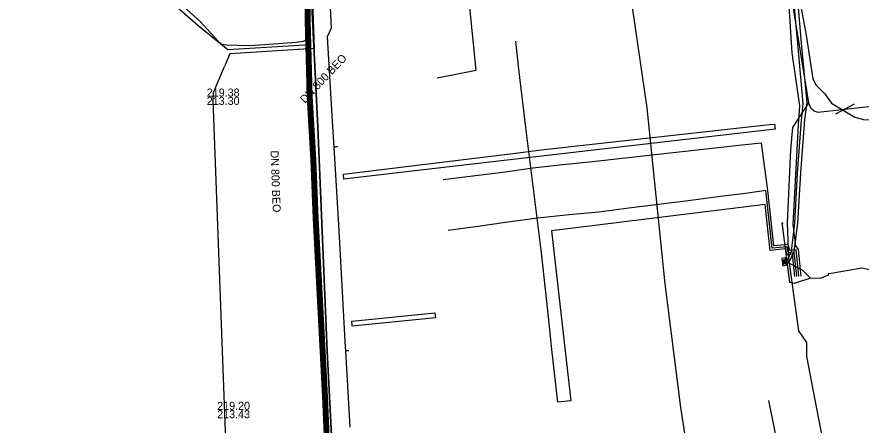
# Model space of a CAD drawing. Extents: x -599951 to -598963, y -1164095 to -1162939.
# Drawn here: x -599256.8 to -599172.5, y -1163441.6 to -1163400.9 of the extents above; entities that cross this region are included whole.
import ezdxf

# ---------------------------------------------------------------- set-up
doc = ezdxf.new("R2010")
doc.units = 0
for name, color, linetype in [('28', 7, 'Continuous'), ('Level 3', 7, 'Continuous'), ('Vrstva 1', 7, 'Continuous'), ('Vrstva 12', 7, 'Continuous'), ('Vrstva 42', 7, 'Continuous'), ('Vrstva 43', 7, 'Continuous'), ('Vrstva 44', 7, 'Continuous'), ('Vrstva 55', 7, 'Continuous'), ('Vrstva 58', 7, 'Continuous')]:
    doc.layers.add(name, color=color, linetype=linetype)

# ---------------------------------------------------------------- blocks, each defined once
blk = doc.blocks.new('NN620')
at = {"layer": '28'}
for points in [[(0.752, 0.004), (-0.748, 0.004)], [(-0.748, 0.004), (-0.748, -0.746)], [(0.752, -0.746), (0.752, 0.004)], [(-0.748, -0.746), (0.752, -0.746)], [(0.368, -0.18), (-0.376, -0.18)], [(-0.376, -0.18), (-0.376, -0.558)], [(-0.376, -0.558), (0.368, -0.558)], [(0.321, -0.227), (-0.329, -0.227)], [(-0.329, -0.227), (-0.329, -0.51)], [(-0.329, -0.51), (0.321, -0.51)], [(0.274, -0.274), (-0.281, -0.274)], [(-0.281, -0.274), (-0.281, -0.463)], [(-0.281, -0.463), (0.274, -0.463)], [(0.227, -0.321), (-0.234, -0.321)], [(-0.234, -0.321), (-0.234, -0.416)], [(-0.234, -0.416), (0.227, -0.416)], [(-0.193, -0.369), (0.185, -0.369)], [(0.227, -0.416), (0.227, -0.321)], [(0.274, -0.463), (0.274, -0.274)], [(0.321, -0.51), (0.321, -0.227)], [(0.368, -0.558), (0.368, -0.18)]]:
    blk.add_lwpolyline(points, dxfattribs=at)

msp = doc.modelspace()

# ---------------------------------------------------------------- linework, layer by layer
at = {"layer": 'Level 3'}
for points in [[(-599181.66, -1163411.62), (-599181.16, -1163411.56), (-599181.1, -1163412.06), (-599216.79, -1163416.18), (-599224.17, -1163417.06), (-599224.2, -1163416.56), (-599216.85, -1163415.68), (-599207.28, -1163414.5), (-599204.46, -1163414.12)], [(-599223.37, -1163431.24), (-599215.08, -1163430.4), (-599215.02, -1163430.9), (-599223.34, -1163431.74)]]:
    msp.add_lwpolyline(points, close=True, dxfattribs=at)
at = {"layer": 'Vrstva 1'}
for p, q in [((-599210.95, -1163406.17), (-599214.67, -1163369.26)), ((-599214.87, -1163406.93), (-599210.95, -1163406.17)), ((-599181.75, -1163439.17), (-599174.22, -1163476.13))]:
    msp.add_line(p, q, dxfattribs=at)
at = {"layer": 'Vrstva 42'}
for p, q in [((-599173.184, -1163409.591), (-599175.046, -1163410.565)), ((-599177.56, -1163426.93), (-599179.2, -1163427.48)), ((-599175.808, -1163426.509), (-599175.79, -1163426.66))]:
    msp.add_line(p, q, dxfattribs=at)
for points in [[(-599224.61, -1163458.23), (-599225.84, -1163434.22), (-599226.77, -1163411.87), (-599227.39, -1163399.73), (-599228, -1163379.96), (-599229.84, -1163349.61), (-599231.04, -1163328.77), (-599232.25, -1163300.34), (-599232.78, -1163281.98), (-599233.12, -1163279.09), (-599233.85, -1163272.58), (-599234.55, -1163261.34), (-599236.04, -1163234.14), (-599238.28, -1163193.96)], [(-599211.757, -1163588.838), (-599211.66, -1163589.578), (-599212.89, -1163589.29), (-599214.35, -1163588.59), (-599214.84, -1163577.9), (-599216.2, -1163560.96), (-599216.62, -1163543.04), (-599219.31, -1163511.2), (-599221.85, -1163490.32), (-599224.61, -1163458.23), (-599225.84, -1163434.22), (-599226.77, -1163411.87), (-599227.39, -1163399.73), (-599228, -1163379.96), (-599229.84, -1163349.61), (-599231.04, -1163328.77), (-599232.25, -1163300.34), (-599232.78, -1163281.98), (-599233.12, -1163279.09), (-599233.85, -1163272.58), (-599234.55, -1163261.34), (-599236.04, -1163234.14), (-599238.28, -1163193.96)], [(-599211.757, -1163588.838), (-599211.66, -1163589.578), (-599212.89, -1163589.29), (-599214.35, -1163588.59), (-599214.84, -1163577.9), (-599216.2, -1163560.96), (-599216.62, -1163543.04), (-599219.31, -1163511.2), (-599221.85, -1163490.32), (-599224.61, -1163458.23), (-599225.84, -1163434.22), (-599226.77, -1163411.87), (-599227.39, -1163399.73), (-599228, -1163379.96), (-599229.84, -1163349.61), (-599231.04, -1163328.77), (-599232.25, -1163300.34), (-599232.78, -1163281.98), (-599233.12, -1163279.09), (-599233.85, -1163272.58), (-599234.55, -1163261.34), (-599236.04, -1163234.14), (-599238.28, -1163193.96)], [(-599214.49, -1163593.34), (-599214.35, -1163588.59), (-599214.84, -1163577.9), (-599216.2, -1163560.96), (-599216.62, -1163543.04), (-599219.31, -1163511.2), (-599221.85, -1163490.32), (-599224.61, -1163458.23), (-599225.84, -1163434.22), (-599226.77, -1163411.87), (-599227.39, -1163399.73), (-599228, -1163379.96), (-599229.84, -1163349.61), (-599231.04, -1163328.77), (-599232.25, -1163300.34), (-599232.78, -1163281.98), (-599233.12, -1163279.09), (-599233.85, -1163272.58), (-599234.55, -1163261.34), (-599236.04, -1163234.14), (-599238.28, -1163193.96)], [(-599214.49, -1163593.34), (-599214.35, -1163588.59), (-599214.84, -1163577.9), (-599216.2, -1163560.96), (-599216.62, -1163543.04), (-599219.31, -1163511.2), (-599221.85, -1163490.32), (-599224.61, -1163458.23), (-599225.84, -1163434.22), (-599226.77, -1163411.87), (-599227.39, -1163399.73), (-599228, -1163379.96), (-599229.84, -1163349.61), (-599231.04, -1163328.77), (-599232.25, -1163300.34), (-599232.78, -1163281.98), (-599233.12, -1163279.09), (-599233.85, -1163272.58), (-599234.55, -1163261.34), (-599236.04, -1163234.14), (-599238.28, -1163193.96)], [(-599224.61, -1163458.23), (-599225.84, -1163434.22), (-599226.77, -1163411.87), (-599227.39, -1163399.73), (-599228, -1163379.96), (-599229.84, -1163349.61), (-599231.04, -1163328.77), (-599232.25, -1163300.34), (-599232.78, -1163281.98), (-599233.12, -1163279.09), (-599233.85, -1163272.58), (-599234.55, -1163261.34), (-599236.04, -1163234.14), (-599238.28, -1163193.96)], [(-599229.322, -1163278.551), (-599233.12, -1163279.09), (-599232.78, -1163281.98), (-599232.25, -1163300.34), (-599231.04, -1163328.77), (-599229.84, -1163349.61), (-599228, -1163379.96), (-599227.39, -1163399.73), (-599226.77, -1163411.87), (-599225.84, -1163434.22), (-599224.61, -1163458.23)], [(-599190.14, -1163320.95), (-599191.11, -1163322.64), (-599190.28, -1163328.52), (-599190.06, -1163330.57), (-599190.68, -1163331.26), (-599188.51, -1163342.56), (-599188.29, -1163343.98), (-599185.98, -1163362.49), (-599184.02, -1163378.38), (-599182.58, -1163394.45), (-599182.18, -1163395.08), (-599179.86, -1163397.7), (-599179.27, -1163398.3), (-599178.66, -1163399.12), (-599178.03, -1163402.48), (-599177.31, -1163407.06), (-599177, -1163407.69)], [(-599179.999, -1163425.339), (-599179.885, -1163425.189), (-599179.74, -1163424.96), (-599179.46, -1163424.24), (-599179.11, -1163421.45), (-599178.85, -1163416.47), (-599178.46, -1163411.18), (-599178.28, -1163409.5), (-599178.83, -1163403.52), (-599179.22, -1163399.16), (-599179.74, -1163396.16), (-599178.925, -1163394.748)], [(-599178.77, -1163394.891), (-599179.5, -1163396.12), (-599178.86, -1163399.14), (-599178.5, -1163403.47), (-599177.93, -1163409.41), (-599178.17, -1163411.12), (-599178.56, -1163416.44), (-599178.84, -1163421.44), (-599179.23, -1163424.29), (-599179.56, -1163425.04), (-599179.816, -1163425.393), (-599179.981, -1163425.494)], [(-599241.11, -1163399.01), (-599238.55, -1163401.29), (-599236.71, -1163403.33), (-599236.38, -1163403.59), (-599235.9, -1163403.66), (-599233.65, -1163403.73), (-599232.06, -1163403.61), (-599228.94, -1163403.38), (-599228.2, -1163403.28), (-599227.89, -1163403.11), (-599227.74, -1163402.67), (-599228.05, -1163397.73)], [(-599177, -1163407.69), (-599176.14, -1163408.56), (-599175.46, -1163409.48), (-599174.31, -1163410.18), (-599173.13, -1163410.88), (-599172.25, -1163411.1), (-599171.56, -1163411.13), (-599167.35, -1163411.12), (-599166.48, -1163411.1), (-599163.47, -1163410.88), (-599162.455, -1163410.965)], [(-599180.39, -1163421.37), (-599180.38, -1163421.4), (-599180.35, -1163421.5)], [(-599179.2, -1163427.48), (-599179.47, -1163427.41), (-599179.64, -1163427.34), (-599179.62, -1163427.33), (-599180.39, -1163421.37)], [(-599175.79, -1163426.66), (-599176.58, -1163426.98), (-599177.56, -1163426.93), (-599178.35, -1163426.15), (-599179.9, -1163425.34)], [(-599164.4, -1163437.31), (-599165.12, -1163432.72), (-599165.45, -1163430.95), (-599165.88, -1163429.98), (-599166.56, -1163429.06), (-599167.76, -1163427.79), (-599169.73, -1163426.5), (-599172.44, -1163425.96), (-599175.3, -1163426.445), (-599175.716, -1163426.498), (-599175.808, -1163426.509)], [(-599169.73, -1163426.5), (-599172.44, -1163425.96), (-599175.3, -1163426.445), (-599175.716, -1163426.498), (-599175.808, -1163426.509)], [(-599175.808, -1163426.509), (-599175.79, -1163426.66), (-599176.58, -1163426.98), (-599177.56, -1163426.93)]]:
    msp.add_lwpolyline(points, dxfattribs=at)
at = {"layer": 'Vrstva 44'}
for points in [[(-599238.757, -1163401.725), (-599246.32, -1163395.11), (-599248.23, -1163393.74), (-599250.84, -1163391.76), (-599251.5, -1163391.09), (-599251.8, -1163390.16), (-599251.93, -1163385.35), (-599252.39, -1163377.35), (-599252.65, -1163369.4), (-599252.9, -1163362.91), (-599253.51, -1163354.83), (-599253.79, -1163347.39), (-599253.99, -1163341.32), (-599254.31, -1163333.85), (-599254.28, -1163327.94), (-599254.76, -1163321.48), (-599255.22, -1163314.42), (-599256.34, -1163305.03), (-599256.84, -1163297.64), (-599256.823, -1163290.889)], [(-599227.34, -1163408.809), (-599227.54, -1163401.199), (-599227.58, -1163393.679), (-599227.21, -1163389.699), (-599227.72, -1163382.299), (-599227.74, -1163380.619), (-599227.912, -1163380.378), (-599228.227, -1163378.968), (-599228.239, -1163378.51), (-599228.469, -1163375.28), (-599228.749, -1163368.07), (-599228.929, -1163364.41), (-599229.499, -1163356.28), (-599230.079, -1163346.28), (-599230.499, -1163338.18), (-599230.839, -1163330.16), (-599231.819, -1163318.58)], [(-599230.467, -1163379.765), (-599228.144, -1163380.56), (-599228.136, -1163380.986), (-599228.12, -1163382.318), (-599227.611, -1163389.708), (-599227.98, -1163393.681), (-599227.94, -1163401.213), (-599227.74, -1163408.828), (-599227.39, -1163415.12), (-599227.13, -1163420.969), (-599226.69, -1163429.82), (-599226.22, -1163438.76), (-599225.759, -1163449.392), (-599225.366, -1163450.807), (-599225.691, -1163452.385), (-599225.19, -1163460.992), (-599224.75, -1163468.141), (-599224.35, -1163476.339), (-599223.968, -1163486.21), (-599223.187, -1163487.477), (-599219.377, -1163491.136)], [(-599230.543, -1163380.39), (-599229.863, -1163380.442), (-599228.727, -1163381.025), (-599228.643, -1163381.866), (-599228.024, -1163390.733), (-599227.547, -1163403.651), (-599235.772, -1163404.164), (-599238.757, -1163401.725)], [(-599230.528, -1163379.968), (-599229.747, -1163380.052), (-599228.351, -1163380.769), (-599228.245, -1163381.832), (-599227.624, -1163390.711), (-599227.133, -1163404.027), (-599235.582, -1163404.545), (-599236.113, -1163405.821)], [(-599225.559, -1163449.38), (-599226.02, -1163438.749), (-599226.49, -1163429.809), (-599226.93, -1163420.958), (-599227.19, -1163415.109), (-599227.54, -1163408.817), (-599227.74, -1163401.202), (-599227.78, -1163393.67), (-599227.411, -1163389.697), (-599227.92, -1163382.307), (-599227.94, -1163380.643)], [(-599235.65, -1163451.2), (-599237.219, -1163409.17), (-599237.183, -1163408.413), (-599236.113, -1163405.821)], [(-599225.36, -1163449.349), (-599225.82, -1163438.739), (-599226.29, -1163429.799), (-599226.73, -1163420.949), (-599226.99, -1163415.099), (-599227.34, -1163408.809)]]:
    msp.add_lwpolyline(points, dxfattribs=at)
at = {"layer": 'Vrstva 55'}
for points in [[(-599183.74, -1163485.49), (-599188.79, -1163450.9), (-599190.5, -1163439.86), (-599192.07, -1163427.52), (-599193.88, -1163409.95), (-599196.91, -1163389.13), (-599198.044, -1163380.488)], [(-599179.95, -1163393.29), (-599180.14, -1163394.15), (-599180.19, -1163395.52), (-599179.69, -1163397.03), (-599179.43, -1163399.17), (-599177.76, -1163409.44), (-599177.738, -1163409.537), (-599177.67, -1163409.723), (-599177.622, -1163409.807), (-599177.571, -1163409.895), (-599177.511, -1163409.974), (-599177.371, -1163410.115), (-599177.293, -1163410.176), (-599177.122, -1163410.277), (-599177.031, -1163410.316), (-599176.84, -1163410.37), (-599171.43, -1163409.79)], [(-599179.95, -1163393.29), (-599180.14, -1163394.15), (-599179.76, -1163395.36), (-599180.16, -1163395.76), (-599179.69, -1163397.03), (-599179.43, -1163399.17), (-599177.76, -1163409.44), (-599179.37, -1163411.92), (-599179.57, -1163414.14), (-599179.89, -1163421.43), (-599179.77, -1163424.95), (-599178.74, -1163432.21), (-599177.95, -1163433.36), (-599177.96, -1163434.77)], [(-599180.19, -1163393.53), (-599180.27, -1163394.36), (-599179.52, -1163395.24), (-599179.54, -1163395.71), (-599179.77, -1163399.24), (-599179.43, -1163404.44), (-599178.64, -1163409.73), (-599178.79, -1163411.64), (-599179.33, -1163421.6), (-599179.061, -1163423.712), (-599178.805, -1163424.078), (-599178.52, -1163426.75)], [(-599225.79, -1163394.96), (-599225.44, -1163401.99), (-599225.83, -1163402.86), (-599225.334, -1163411.264), (-599225.18, -1163413.87), (-599224.822, -1163413.798), (-599225.18, -1163413.87), (-599224.722, -1163421.627), (-599224.58, -1163424.03), (-599224.035, -1163433.816), (-599224.014, -1163434.201), (-599223.667, -1163434.15), (-599224.014, -1163434.201), (-599223.59, -1163441.83)], [(-599179.12, -1163426.781), (-599179.356, -1163424.564), (-599179.896, -1163424.644), (-599180.07, -1163424.02), (-599181.577, -1163424.169), (-599182.08, -1163419.58), (-599203.42, -1163422.22), (-599201.51, -1163439.19), (-599202.809, -1163439.331), (-599203.097, -1163436.697), (-599203.384, -1163434.063), (-599203.671, -1163431.428), (-599204.04, -1163428.048), (-599204.436, -1163424.42), (-599206.035, -1163411.628), (-599206.357, -1163408.847), (-599206.679, -1163406.066), (-599207.001, -1163403.284)], [(-599178.72, -1163426.76), (-599179.003, -1163424.108), (-599179.605, -1163424.197), (-599179.775, -1163423.589), (-599181.222, -1163423.732), (-599181.829, -1163418.185), (-599182.44, -1163413.46), (-599184.413, -1163413.682), (-599187.395, -1163414.009), (-599190.377, -1163414.336), (-599193.359, -1163414.663), (-599196.342, -1163414.99), (-599199.324, -1163415.317), (-599202.306, -1163415.644), (-599205.288, -1163415.971), (-599208.304, -1163416.39), (-599211.282, -1163416.757), (-599214.259, -1163417.128)], [(-599178.92, -1163426.77), (-599179.18, -1163424.336), (-599179.751, -1163424.42), (-599179.923, -1163423.804), (-599181.399, -1163423.95), (-599182.028, -1163418.207), (-599183.809, -1163418.46), (-599186.785, -1163418.837), (-599189.762, -1163419.213), (-599192.738, -1163419.589), (-599195.714, -1163419.966), (-599198.69, -1163420.342), (-599201.65, -1163420.62), (-599204.816, -1163420.94), (-599207.787, -1163421.357), (-599210.758, -1163421.773), (-599213.759, -1163422.184)], [(-599177.96, -1163434.77), (-599172.809, -1163461.537)]]:
    msp.add_lwpolyline(points, dxfattribs=at)
at = {"layer": 'Vrstva 58'}
for points in [[(-599223.108, -1163487.413), (-599223.869, -1163486.18), (-599224.25, -1163476.334), (-599224.65, -1163468.135), (-599225.09, -1163460.986), (-599225.591, -1163452.393), (-599225.263, -1163450.803), (-599225.659, -1163449.376), (-599226.12, -1163438.755), (-599226.59, -1163429.815), (-599227.03, -1163420.965), (-599227.29, -1163415.115), (-599227.64, -1163408.824), (-599227.84, -1163401.212), (-599227.88, -1163393.686), (-599227.51, -1163389.709), (-599228.02, -1163382.314), (-599228.04, -1163380.642), (-599228.188, -1163380.463), (-599228.529, -1163379.006), (-599228.539, -1163378.515), (-599228.77, -1163375.275), (-599228.891, -1163372.22)], [(-599222.952, -1163487.287), (-599223.671, -1163486.12), (-599224.05, -1163476.326), (-599224.45, -1163468.124), (-599224.89, -1163460.974), (-599225.389, -1163452.407), (-599225.057, -1163450.797), (-599225.461, -1163449.344), (-599225.92, -1163438.745), (-599226.39, -1163429.805), (-599226.83, -1163420.955), (-599227.09, -1163415.105), (-599227.44, -1163408.816), (-599227.64, -1163401.208), (-599227.68, -1163393.694), (-599227.31, -1163389.711), (-599227.82, -1163382.306), (-599227.84, -1163380.618), (-599228.01, -1163380.408), (-599228.334, -1163378.977), (-599228.341, -1163378.485), (-599228.57, -1163375.264), (-599228.69, -1163372.211)], [(-599230.532, -1163379.85), (-599228.243, -1163380.632), (-599228.236, -1163380.987), (-599228.22, -1163382.322), (-599227.711, -1163389.706), (-599228.08, -1163393.677), (-599228.04, -1163401.215), (-599227.84, -1163408.832), (-599227.49, -1163415.125), (-599227.23, -1163420.974), (-599226.79, -1163429.825), (-599226.32, -1163438.764), (-599225.858, -1163449.407), (-599225.468, -1163450.81), (-599225.792, -1163452.378), (-599225.289, -1163460.998), (-599224.85, -1163468.147), (-599224.45, -1163476.343), (-599224.067, -1163486.24), (-599223.265, -1163487.54)]]:
    msp.add_lwpolyline(points, dxfattribs=at)

# ---------------------------------------------------------------- block references
at = {"layer": 'Vrstva 43', "xscale": 0.5000000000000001, "yscale": 0.5000000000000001, "rotation": -82}
msp.add_blockref('NN620', (-599180, -1163425.29), dxfattribs=at)

# ---------------------------------------------------------------- texts
at = {"layer": 'Vrstva 12'}
for rotation, p in [(46.69606, (-599228.062, -1163409.543)), (272.09766, (-599231.499, -1163414.215))]:
    msp.add_text('DN 800 BEO', height=0.8, rotation=rotation, dxfattribs=at).set_placement(p)
for s, p in [('219.38', (-599237.867, -1163408.817)), ('213.30', (-599237.867, -1163409.649)), ('219.20', (-599236.825, -1163440.086)), ('213.43', (-599236.825, -1163440.918))]:
    msp.add_text(s, height=0.8, dxfattribs=at).set_placement(p)

doc.saveas('drawing.dxf')
